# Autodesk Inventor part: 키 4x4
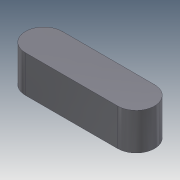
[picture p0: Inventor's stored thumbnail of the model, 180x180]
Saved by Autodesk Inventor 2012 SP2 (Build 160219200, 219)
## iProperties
Company: 한국ATC센터
Created: 2014-10
Part Number: 키 4x4
Document SubType Name: Modeling
Designer: KYOUNG IL JANG
Density: 1 g/cm^3
Mass: 0.210265 g
Surface Area: 2.35398 cm^2
Volume: 0.210265 cm^3
Material: 기본값
Author: KYOUNG IL JANG
Revision Number: 1
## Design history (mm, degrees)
sketch "스케치1"
  geometry: L1 (-5, -2)-(5, -2); L2 (5, 2)-(-5, 2); A1 r 2 centre (5, 0) between (5, -2) and (5, 2); A2 r 2 centre (-5, 0) between (-5, 2) and (-5, -2); 2 further points
  constraints: 4 end point, 4 point on circle, 4 tangent, 2 centre point, 1 horizontal, 1 horizontal alignment, 1 midpoint, 1 parallel, 1 vertical alignment
  dimensions: "d0" = 4 distance between parallel lines of L1 L2; "d1" = 14 dimension on A1 A2
extrude "돌출1" new body sketch "스케치1" stored distance "d2" = 4; taper "d3" = 0 deg
node "솔리드1"
